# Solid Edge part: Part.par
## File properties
Accuracy: 0.99
Author: CADCIM
Template: normal.par
Last saved by: Rajat Kamboj
Revision: 18
Application: Solid Edge
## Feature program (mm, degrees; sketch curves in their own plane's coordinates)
sketch for "unnamed Protrusion 1" plane through (0, 0, 0) normal (0, 0, 1) x-axis (1, 0, 0)
  line (-63.0032, 49) -> (-56, -71)
  line (-56, -71) -> (56, -71)
  line (56, -71) -> (63.0032, 49)
  line (63.0032, 49) -> (0, 54)
  line (0, 54) -> (-63.0032, 49)
  dimension (linear) = 56
  dimension (linear) = 56
extrude "unnamed Protrusion 1" add finite 4 along +normal
fillet "Round_1" radius 15
sketch for "ExtrudedProtrusion_3" plane through (0, -8.5, 0) normal (0, 0, -1) x-axis (-1, 0, 0)
extrude "ExtrudedProtrusion_3" add finite 12 along -normal
pattern "unnamed Pattern 1" of "ExtrudedProtrusion_3"
pattern "unnamed Pattern 2"
sketch for "unnamed Protrusion 2" plane through (-1.0316, 2.3101, 4) normal (0, 0, 1) x-axis (-1, 0, 0)
extrude "unnamed Protrusion 2" add finite 5 along +normal
sketch for "Hole_22" plane through (40.9331, -54.9887, 12) normal (0, 0, 1) x-axis (1, 0, 0)
  hole centre (-0.4331, -0.0113) bore radius 4.5
hole "Hole_22" diameter 9 through  CounterBoreDepth = 5 mm
pattern "unnamed Pattern 3" of "Hole_22"
hole "unnamed Hole 1" through
hole "unnamed Hole 2" through
hole "unnamed Hole 3" through
sketch for "Hole_29" plane through (-1.0316, -6.1899, 9) normal (0, 0, 1) x-axis (1, 0, 0)
hole "Hole_29" diameter 22 through
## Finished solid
Body 1: solid body, 34 faces, 55 edges, 18 vertices.
  Faces by surface: cylinder 18, plane 16
  Edges by curve: circle 36, line 19
Bounding box of the edges (mm): 124.346 x 125.000 x 12.000, from (-62.1729, -71, 0) to (62.1729, 54, 12).
Cylindrical faces by radius (mm): R4.5 x4, R7.5 x4, R10.7006 x4, R11 x1, R15 x4, R20 x1
Planar faces by outward normal: +z 10, -y 1, -z 1, oblique 4
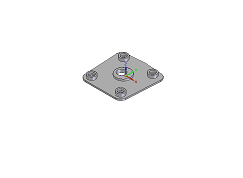
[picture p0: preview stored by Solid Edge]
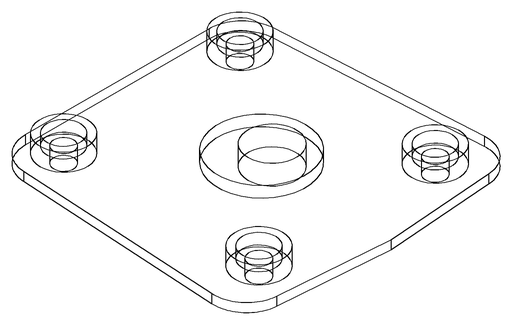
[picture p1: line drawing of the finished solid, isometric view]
